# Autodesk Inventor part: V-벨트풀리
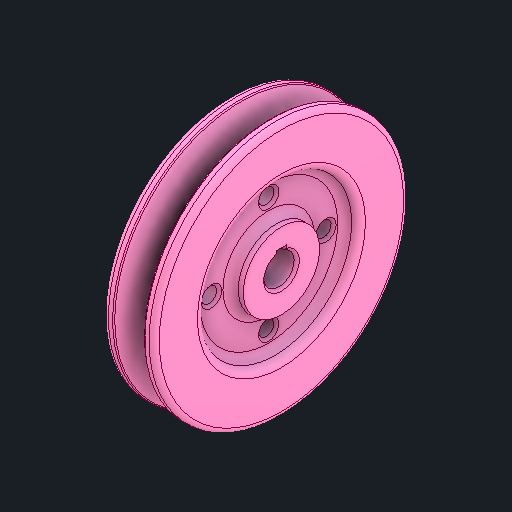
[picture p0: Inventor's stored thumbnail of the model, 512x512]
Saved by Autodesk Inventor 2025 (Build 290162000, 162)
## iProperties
Created: 2025-08
Part Number: V-벨트풀리
Material: 강철, 연강
Document SubType Name: Modeling
Designer: infra11
Density: 7.86 g/cm^3
Appearance: 기본값
Author: jhkim
Sending System: Autodesk Inventor 2026
Preprocessor: ST-DEVELOPER v20.1
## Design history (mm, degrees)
feature "솔리드1"
node "솔리드2"
